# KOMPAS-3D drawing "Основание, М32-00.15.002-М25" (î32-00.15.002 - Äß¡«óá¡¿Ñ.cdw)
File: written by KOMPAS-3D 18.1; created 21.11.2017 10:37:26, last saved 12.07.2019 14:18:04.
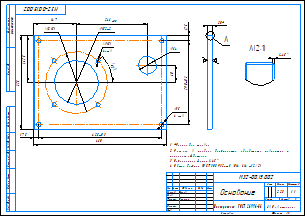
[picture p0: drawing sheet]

Sheet 1: A3, landscape

Document properties: Полное имя файла: D:\Magna\Магна Ins\Магна ins 32\Для Караби\М32-00.15.002 - Основание.cdw; Масса: 2.27958

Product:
- Part/product: Основание  | designation М32-00.15.002-М25
    Материал: Полипропилен  ГОСТ 26996-86 (density 900 kg/m3)
    Масса: 1.82071
    Раздел спецификации: Детали
    Форматы листов документа: A3
- Part/product: Основание  | designation М32-10.15.002-ПВХ
    Материал: Полипропилен  ГОСТ 26996-86 (density 900 kg/m3)
    Масса: 2.27958
    Раздел спецификации: Детали
    Форматы листов документа: A3
- Part/product: Основание  | designation М32-00.15.002
    Материал: Полипропилен  ГОСТ 26996-86 (density 900 kg/m3)
    Масса: 2.27958
    Раздел спецификации: Детали
    Форматы листов документа: A3
    source file: М32-00.15.002 - Основание.cdw, М32-00.15.002-М25 - Основание.cdw

Title block, sheet 1: Наименование: Основание; designation: М32-00.15.002; Материал: Полипропилен  ГОСТ 26996-86; Масса: 2,28; scale: 1:1; Количество листов документа: 1; organisation: ЗАО «Астерион»; Форматы листов документа: A3; stored path: D:\Отработать\Магна 40\Чертежи\М40-00.15.002 - Основание.cdw; Разработал: Милов; Т. контр.: Лучихин

Views: Вид 1, Спереди, Проекционный вид 2, Выносной элемент 3, Выносной элемент А, Выносной элемент
Referenced files in D:\Отработать\Магна 40\3Д\: М40-00.15.002 - Основание.m3d
Referenced files in Z:\Магна\Магна Ins\Магна ins 32\: М32-00.15.002 - Основание.m3d
Referenced files in D:\Magna\Магна Ins\Магна ins 32\Для Караби\: М32-00.15.002 - Основание.m3d
Dimensions and other numbers on the sheet: 60; 162,5; 152±2; 215; 15; 4отв.; 64; 147; 246; 460; 325; 4 отв.; 425±0,3; 17,5; 290±0,3; 20; 1; 1:1; 2,28

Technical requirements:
  *Размер для справок.
  Размеры в скобках допускается обработать совместно с
  сопрягаемой деталью.
  Неуказанные фаски 1х45 .
  Общие допуски ГОСТ 30893.2-тК (H14, h14,  t2/2).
